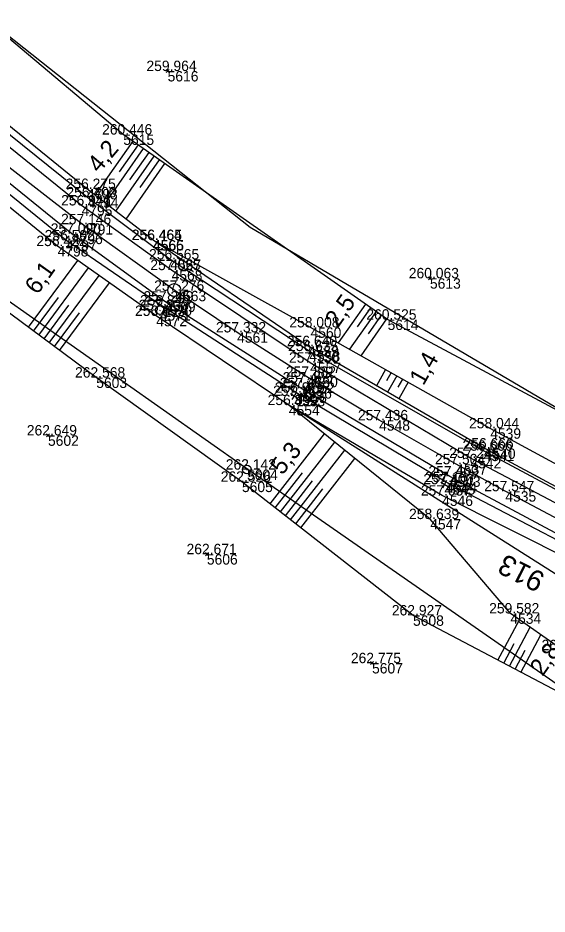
# Model space of a CAD drawing. Extents: x -809970 to -809480, y -1011362 to -1010672.
# Drawn here: x -809711.9 to -809650.7, y -1011259.5 to -1011155.9 of the extents above; entities that cross this region are included whole.
import ezdxf

# ---------------------------------------------------------------- set-up
doc = ezdxf.new("R2010")
doc.units = 0
for name, color, linetype in [('Vrstva 1', 7, 'Continuous'), ('Vrstva 4', 7, 'Continuous'), ('Vrstva 48', 7, 'Continuous'), ('Vrstva 49', 7, 'Continuous'), ('Vrstva 53', 7, 'Continuous'), ('Vrstva 60', 7, 'Continuous'), ('Vrstva 61', 7, 'Continuous'), ('Vrstva 63', 7, 'Continuous'), ('Vrstva 7', 7, 'Continuous')]:
    doc.layers.add(name, color=color, linetype=linetype)

msp = doc.modelspace()

# ---------------------------------------------------------------- linework, layer by layer
at = {"layer": 'Vrstva 1'}
msp.add_lwpolyline([(-809626.11, -1011225.69), (-809635.65, -1011220.96), (-809646.77, -1011215.28), (-809655.53, -1011210.64), (-809661.22, -1011207.52), (-809670.13, -1011202.44), (-809678.48, -1011197.41), (-809686.56, -1011192.28), (-809693.71, -1011187.47), (-809704.48, -1011179.77), (-809716.3, -1011170.61)], dxfattribs=at)
at = {"layer": 'Vrstva 4'}
for points in [[(-809514.07, -1011276.67), (-809539.83, -1011264.26), (-809562.29, -1011253.6), (-809585.06, -1011242.59), (-809604.03, -1011233.74), (-809622.75, -1011224.34), (-809635.98, -1011217.78), (-809658.04, -1011205.96), (-809678.21, -1011194.44), (-809694.3, -1011183.84), (-809703.86, -1011176.66), (-809724.9, -1011159.78), (-809744.11, -1011141.6), (-809762.15, -1011122.16), (-809774.57, -1011106.33), (-809789.63, -1011085.97), (-809801.28, -1011067.08), (-809811.54, -1011048.02), (-809817.16, -1011036.69), (-809823.08, -1011022.98)], [(-809514.73, -1011277.55), (-809539.87, -1011265.31), (-809562.72, -1011254.42), (-809585.31, -1011243.69), (-809604.51, -1011234.26), (-809623.3, -1011225.16), (-809636.52, -1011218.94), (-809659.57, -1011206.8), (-809678.11, -1011195.78), (-809694.14, -1011185.08), (-809704.56, -1011177.6), (-809725.72, -1011160.53), (-809745.22, -1011142.43), (-809763.07, -1011123.23), (-809775.62, -1011107.42), (-809790.76, -1011086.7), (-809802.43, -1011068.09), (-809812.88, -1011048.59), (-809818.37, -1011037.45), (-809824.5, -1011023.86)], [(-809516.72, -1011279.86), (-809541.72, -1011267.84), (-809564.36, -1011257.13), (-809585.64, -1011247.05), (-809605.96, -1011237.21), (-809624.35, -1011228.4), (-809638.66, -1011221.38), (-809661.97, -1011208.93), (-809679.17, -1011198.73), (-809694.94, -1011188.71), (-809705.67, -1011180.87), (-809727.9, -1011162.91), (-809747.29, -1011144.85), (-809765.46, -1011125.12), (-809778.44, -1011109.55), (-809793.36, -1011088.57), (-809805.27, -1011069.6), (-809816.07, -1011050.21), (-809821.49, -1011039.16), (-809826.21, -1011028.82)], [(-809517.34, -1011281.17), (-809542.25, -1011268.91), (-809565.05, -1011257.74), (-809585.85, -1011248.03), (-809606.19, -1011237.96), (-809624.44, -1011229.46), (-809639.03, -1011221.78), (-809662.37, -1011209.59), (-809679.75, -1011199.24), (-809695.35, -1011189.16), (-809706.37, -1011181.63), (-809728.71, -1011163.52), (-809748.04, -1011145.82), (-809766.46, -1011126.18), (-809779.35, -1011110.29), (-809779.4, -1011110.26), (-809794.33, -1011089.31), (-809806.51, -1011070.34), (-809817.46, -1011050.77), (-809822.78, -1011039.81), (-809827.65, -1011029.26)]]:
    msp.add_lwpolyline(points, dxfattribs=at)
at = {"layer": 'Vrstva 48'}
for p, q in [((-809698.64, -1011170.17), (-809703.01, -1011176.41)), ((-809698.02, -1011170.59), (-809700.22, -1011173.73)), ((-809697.41, -1011171.03), (-809701.82, -1011177.33)), ((-809696.18, -1011171.89), (-809700.63, -1011178.25)), ((-809696.79, -1011171.46), (-809699.01, -1011174.62)), ((-809694.95, -1011172.74), (-809699.44, -1011179.17)), ((-809695.56, -1011172.32), (-809697.8, -1011175.51)), ((-809710.71, -1011191.69), (-809704.98, -1011183.96)), ((-809709.5, -1011192.58), (-809703.76, -1011184.83)), ((-809708.3, -1011193.47), (-809702.53, -1011185.69)), ((-809707.09, -1011194.36), (-809701.31, -1011186.56)), ((-809710.1, -1011192.13), (-809707.24, -1011188.26)), ((-809708.9, -1011193.03), (-809706.02, -1011189.14)), ((-809671.72, -1011189), (-809674.87, -1011193.5)), ((-809671.11, -1011189.44), (-809672.66, -1011191.65)), ((-809707.69, -1011193.92), (-809704.81, -1011190.02)), ((-809670.49, -1011189.86), (-809673.55, -1011194.23)), ((-809669.88, -1011190.3), (-809671.39, -1011192.45)), ((-809669.26, -1011190.72), (-809672.24, -1011194.97)), ((-809669.4, -1011196.57), (-809670.45, -1011198.44)), ((-809668.74, -1011196.93), (-809669.27, -1011197.88)), ((-809668.09, -1011197.3), (-809669.15, -1011199.19)), ((-809667.44, -1011197.67), (-809667.97, -1011198.62)), ((-809666.78, -1011198.04), (-809667.85, -1011199.94)), ((-809682.74, -1011212.09), (-809676.44, -1011204.02)), ((-809681.56, -1011213.01), (-809675.27, -1011204.96)), ((-809680.37, -1011213.93), (-809674.1, -1011205.9)), ((-809679.19, -1011214.86), (-809672.93, -1011206.84)), ((-809682.15, -1011212.55), (-809679, -1011208.52)), ((-809680.96, -1011213.47), (-809677.82, -1011209.45)), ((-809679.78, -1011214.4), (-809676.65, -1011210.38)), ((-809656.38, -1011230.18), (-809653.91, -1011225.5)), ((-809655.05, -1011230.88), (-809652.67, -1011226.37)), ((-809653.72, -1011231.58), (-809651.44, -1011227.23)), ((-809655.72, -1011230.53), (-809654.51, -1011228.23)), ((-809654.39, -1011231.23), (-809653.22, -1011229.01))]:
    msp.add_line(p, q, dxfattribs=at)
at = {"layer": 'Vrstva 49'}
for p, q in [((-809694.78, -1011161.89), (-809694.42, -1011162.24)), ((-809694.78, -1011162.24), (-809694.42, -1011161.89)), ((-809664.43, -1011185.85), (-809664.07, -1011186.2)), ((-809664.43, -1011186.2), (-809664.07, -1011185.85)), ((-809708.61, -1011204.01), (-809708.26, -1011204.36)), ((-809708.61, -1011204.36), (-809708.26, -1011204.01)), ((-809690.23, -1011217.74), (-809689.88, -1011218.1)), ((-809690.23, -1011218.1), (-809689.88, -1011217.74)), ((-809671.12, -1011230.34), (-809670.77, -1011230.69)), ((-809671.12, -1011230.69), (-809670.77, -1011230.34))]:
    msp.add_line(p, q, dxfattribs=at)
for points in [[(-809511.61, -1011271.23), (-809536.39, -1011258.33), (-809560.01, -1011246.27), (-809576.21, -1011238.32), (-809612.21, -1011219.9), (-809615.12, -1011217.12), (-809615.79, -1011215.73), (-809619.54, -1011223.55), (-809624.01, -1011221.32), (-809620.33, -1011213.39), (-809626.47, -1011211.63), (-809636.4, -1011208.19), (-809641.71, -1011205.47), (-809669.15, -1011190.8), (-809699.73, -1011169.4), (-809726.54, -1011146.85), (-809748.5, -1011124.91), (-809769.57, -1011100.55), (-809784.98, -1011078.51), (-809794.37, -1011063.91), (-809798.01, -1011059.09), (-809806.77, -1011045.25), (-809814.25, -1011034.46), (-809820.96, -1011021.87)], [(-809517.95, -1011282.18), (-809542.49, -1011269.58), (-809565.63, -1011258.32), (-809585.98, -1011248.4), (-809606.44, -1011238.24), (-809621.62, -1011231.05), (-809624.45, -1011230.4), (-809627.73, -1011228.86), (-809639.59, -1011222.81), (-809662.84, -1011211.14), (-809680.58, -1011200.68), (-809695.92, -1011190.37), (-809707.33, -1011182.3), (-809729.57, -1011164.32), (-809748.84, -1011146.41), (-809766.98, -1011126.93), (-809779.99, -1011110.78), (-809794.75, -1011089.67), (-809807.08, -1011070.6), (-809818.27, -1011051.22), (-809824.25, -1011040.29), (-809829.11, -1011030.23)], [(-809513.01, -1011276.14), (-809534.58, -1011266.09), (-809539.77, -1011263.86), (-809561.92, -1011253.16), (-809584.64, -1011241.91), (-809603.49, -1011232.88), (-809619.73, -1011225.04), (-809620.87, -1011223.99), (-809623.85, -1011222.57), (-809625.32, -1011222.49), (-809635.81, -1011217.56), (-809657.91, -1011205.7), (-809678.34, -1011193.87), (-809696.27, -1011181.61), (-809696.31, -1011181.59), (-809703.94, -1011175.69), (-809724.27, -1011159.21)], [(-809624.01, -1011221.32), (-809625.48, -1011221.25), (-809635.66, -1011215.12), (-809657.28, -1011203.37), (-809678.07, -1011191.7), (-809696.27, -1011181.61), (-809696.31, -1011181.59)], [(-809528.41, -1011284.67), (-809557.05, -1011271.63), (-809578.05, -1011261.94), (-809594.42, -1011254.32), (-809626.26, -1011240.21), (-809627.58, -1011240.01), (-809623.67, -1011231.94), (-809628.13, -1011229.78), (-809632.16, -1011237.96), (-809631.7, -1011238.19), (-809633.92, -1011240.11), (-809638.94, -1011239.66), (-809644.87, -1011236.23), (-809666.21, -1011225), (-809686, -1011209.54), (-809702.86, -1011197.5), (-809722.79, -1011182.74)], [(-809628.13, -1011229.78), (-809630.07, -1011228.4), (-809632.43, -1011226.95), (-809647.88, -1011221.39), (-809680.58, -1011200.68)], [(-809632.16, -1011237.96), (-809640.18, -1011233.65), (-809648.89, -1011229.02), (-809654.95, -1011224.77), (-809664.22, -1011213.86), (-809680.58, -1011200.68)]]:
    msp.add_lwpolyline(points, dxfattribs=at)
at = {"layer": 'Vrstva 53'}
msp.add_line((-809685.46, -1011208.11), (-809685.38, -1011208.16), dxfattribs=at)
for points in [[(-809817.83, -1011024.91), (-809805.06, -1011048.21), (-809777.13, -1011090.84), (-809773.31, -1011095.41), (-809752.3, -1011120.38), (-809722.41, -1011150.52), (-809685.06, -1011180.11), (-809638.61, -1011207.44), (-809624.45, -1011211.08), (-809620, -1011212.86), (-809615.56, -1011215.28), (-809614.76, -1011215.85), (-809598.39, -1011227.55), (-809488.36, -1011283.38)], [(-809479.96, -1011306.98), (-809541.53, -1011278.39), (-809624.88, -1011241.51), (-809627.72, -1011240.25), (-809632.39, -1011238.49), (-809632.72, -1011238.43), (-809644.97, -1011236.14), (-809685.42, -1011208.04), (-809719.22, -1011184.3), (-809751.99, -1011157.11), (-809779.01, -1011125.97), (-809796.54, -1011101.19), (-809810.89, -1011076.81), (-809836.26, -1011028.53)]]:
    msp.add_lwpolyline(points, dxfattribs=at)
msp.add_circle((-809685.42, -1011208.14), 0.499, dxfattribs=at)
at = {"layer": 'Vrstva 60'}
for p, q in [((-809694.6, -1011162.06), (-809694.6, -1011162.06)), ((-809699.73, -1011169.4), (-809699.73, -1011169.4)), ((-809703.94, -1011175.69), (-809703.94, -1011175.69)), ((-809703.86, -1011176.66), (-809703.86, -1011176.66)), ((-809704.56, -1011177.6), (-809704.56, -1011177.6)), ((-809704.48, -1011179.77), (-809704.48, -1011179.77)), ((-809705.67, -1011180.87), (-809705.67, -1011180.87)), ((-809707.33, -1011182.3), (-809707.33, -1011182.3)), ((-809706.37, -1011181.63), (-809706.37, -1011181.63)), ((-809696.31, -1011181.59), (-809696.31, -1011181.59)), ((-809696.27, -1011181.61), (-809696.27, -1011181.61)), ((-809694.3, -1011183.84), (-809694.3, -1011183.84)), ((-809694.14, -1011185.08), (-809694.14, -1011185.08)), ((-809664.25, -1011186.02), (-809664.25, -1011186.02)), ((-809693.71, -1011187.47), (-809693.71, -1011187.47)), ((-809695.35, -1011189.16), (-809695.35, -1011189.16)), ((-809694.94, -1011188.71), (-809694.94, -1011188.71)), ((-809695.92, -1011190.37), (-809695.92, -1011190.37)), ((-809695.5, -1011189.71), (-809695.5, -1011189.71)), ((-809669.15, -1011190.8), (-809669.15, -1011190.8)), ((-809686.56, -1011192.28), (-809686.56, -1011192.28)), ((-809678.07, -1011191.7), (-809678.07, -1011191.7)), ((-809678.34, -1011193.87), (-809678.34, -1011193.87)), ((-809678.21, -1011194.44), (-809678.21, -1011194.44)), ((-809678.11, -1011195.78), (-809678.11, -1011195.78)), ((-809702.86, -1011197.5), (-809702.86, -1011197.5)), ((-809678.48, -1011197.41), (-809678.48, -1011197.41)), ((-809679.17, -1011198.73), (-809679.17, -1011198.73)), ((-809678.83, -1011198.07), (-809678.83, -1011198.07)), ((-809679.95, -1011199.62), (-809679.95, -1011199.62)), ((-809679.75, -1011199.24), (-809679.75, -1011199.24)), ((-809680.58, -1011200.68), (-809680.58, -1011200.68)), ((-809670.13, -1011202.44), (-809670.13, -1011202.44)), ((-809657.28, -1011203.37), (-809657.28, -1011203.37)), ((-809708.44, -1011204.19), (-809708.44, -1011204.19)), ((-809658.04, -1011205.96), (-809658.04, -1011205.96)), ((-809657.91, -1011205.7), (-809657.91, -1011205.7)), ((-809659.57, -1011206.8), (-809659.57, -1011206.8)), ((-809685.42, -1011208.14), (-809685.42, -1011208.14)), ((-809661.22, -1011207.52), (-809661.22, -1011207.52)), ((-809661.97, -1011208.93), (-809661.97, -1011208.93)), ((-809686, -1011209.54), (-809686, -1011209.54)), ((-809662.57, -1011209.83), (-809662.57, -1011209.83)), ((-809662.37, -1011209.59), (-809662.37, -1011209.59)), ((-809662.84, -1011211.14), (-809662.84, -1011211.14)), ((-809655.53, -1011210.64), (-809655.53, -1011210.64)), ((-809664.22, -1011213.86), (-809664.22, -1011213.86)), ((-809690.06, -1011217.92), (-809690.06, -1011217.92)), ((-809654.95, -1011224.77), (-809654.95, -1011224.77)), ((-809666.21, -1011225), (-809666.21, -1011225)), ((-809670.95, -1011230.52), (-809670.95, -1011230.52))]:
    msp.add_line(p, q, dxfattribs=at)
at = {"layer": 'Vrstva 7'}
for p, q in [((-809695.54, -1011189.69), (-809695.46, -1011189.74)), ((-809680.37, -1011199.35), (-809679.53, -1011199.89)), ((-809679.68, -1011199.19), (-809680.22, -1011200.04)), ((-809663, -1011209.58), (-809662.13, -1011210.08)), ((-809662.32, -1011209.4), (-809662.81, -1011210.27))]:
    msp.add_line(p, q, dxfattribs=at)
for centre, radius in [((-809693.84, -1011187.38), 0.75), ((-809695.5, -1011189.71), 0.5)]:
    msp.add_circle(centre, radius, dxfattribs=at)

# ---------------------------------------------------------------- texts
at = {"layer": 'Vrstva 48'}
for s, rotation, p in [('4,2', 49.937, (-809702.54, -1011173.94)), ('6,1', 54.7503, (-809709.65, -1011188)), ('2,5', 55.0089, (-809674.91, -1011191.84)), ('1,4', 60.6951, (-809665.01, -1011198.52)), ('5,3', 51.1502, (-809681.34, -1011208.86)), ('2,8', 54.9661, (-809651.22, -1011232.13))]:
    msp.add_text(s, height=2, rotation=rotation, dxfattribs=at).set_placement(p)
at = {"layer": 'Vrstva 60'}
for s, p in [('5616', (-809694.6, -1011163.26)), ('5615', (-809699.73, -1011170.6)), ('4793', (-809703.94, -1011176.89)), ('4794', (-809703.86, -1011177.86)), ('4795', (-809704.56, -1011178.8)), ('4791', (-809704.48, -1011180.97)), ('4796', (-809705.67, -1011182.07)), ('4798', (-809707.33, -1011183.5)), ('4797', (-809706.37, -1011182.83)), ('4566', (-809696.31, -1011182.79)), ('4565', (-809696.27, -1011182.81)), ('4567', (-809694.3, -1011185.04)), ('4568', (-809694.14, -1011186.28)), ('5613', (-809664.25, -1011187.22)), ('4563', (-809693.71, -1011188.67)), ('4570', (-809695.35, -1011190.36)), ('4569', (-809694.94, -1011189.92)), ('4572', (-809695.92, -1011191.57)), ('4571', (-809695.5, -1011190.91)), ('5614', (-809669.15, -1011192)), ('4561', (-809686.56, -1011193.47)), ('4560', (-809678.07, -1011192.9)), ('4559', (-809678.34, -1011195.07)), ('4558', (-809678.21, -1011195.64)), ('4557', (-809678.11, -1011196.98)), ('5603', (-809702.86, -1011198.7)), ('4550', (-809678.48, -1011198.61)), ('4556', (-809679.17, -1011199.93)), ('4552', (-809678.83, -1011199.27)), ('4553', (-809679.95, -1011200.82)), ('4555', (-809679.75, -1011200.44)), ('4554', (-809680.58, -1011201.88)), ('4548', (-809670.13, -1011203.64)), ('4539', (-809657.28, -1011204.57)), ('5602', (-809708.44, -1011205.39)), ('4541', (-809658.04, -1011207.16)), ('4540', (-809657.91, -1011206.9)), ('4542', (-809659.57, -1011208)), ('5604', (-809685.42, -1011209.34)), ('4537', (-809661.22, -1011208.72)), ('4543', (-809661.97, -1011210.13)), ('5605', (-809686, -1011210.74)), ('4545', (-809662.57, -1011211.03)), ('4544', (-809662.37, -1011210.79)), ('4546', (-809662.84, -1011212.34)), ('4535', (-809655.53, -1011211.84)), ('4547', (-809664.22, -1011215.06)), ('5606', (-809690.06, -1011219.12)), ('4534', (-809654.95, -1011225.97)), ('5608', (-809666.21, -1011226.2)), ('5607', (-809670.95, -1011231.71))]:
    msp.add_text(s, height=1.2, dxfattribs=at).set_placement(p)
at = {"layer": 'Vrstva 61'}
for s, p in [('259.964', (-809697.05, -1011162.06)), ('260.446', (-809702.18, -1011169.4)), ('256.275', (-809706.4, -1011175.69)), ('256.400', (-809706.31, -1011176.66)), ('256.941', (-809706.92, -1011177.6)), ('257.146', (-809706.93, -1011179.77)), ('257.090', (-809708.12, -1011180.87)), ('256.422', (-809709.78, -1011182.3)), ('256.502', (-809708.82, -1011181.63)), ('256.464', (-809698.76, -1011181.59)), ('256.465', (-809698.73, -1011181.61)), ('256.565', (-809696.75, -1011183.84)), ('257.025', (-809696.6, -1011185.08)), ('260.063', (-809666.7, -1011186.02)), ('257.276', (-809696.16, -1011187.47)), ('257.249', (-809697.4, -1011188.71)), ('257.233', (-809697.95, -1011189.71)), ('256.840', (-809697.8, -1011189.16)), ('256.853', (-809698.37, -1011190.37)), ('258.008', (-809680.52, -1011191.7)), ('260.525', (-809671.61, -1011190.8)), ('257.332', (-809689.01, -1011192.28)), ('256.640', (-809680.8, -1011193.87)), ('256.635', (-809680.66, -1011194.44)), ('257.130', (-809680.56, -1011195.78)), ('262.568', (-809705.31, -1011197.5)), ('257.382', (-809680.92, -1011197.41)), ('257.378', (-809681.63, -1011198.73)), ('257.485', (-809681.29, -1011198.07)), ('257.163', (-809682.4, -1011199.62)), ('256.979', (-809682.2, -1011199.24)), ('256.899', (-809683.03, -1011200.68)), ('257.436', (-809672.58, -1011202.44)), ('262.649', (-809710.89, -1011204.19)), ('258.044', (-809659.73, -1011203.37)), ('256.666', (-809660.49, -1011205.96)), ('256.666', (-809660.36, -1011205.7)), ('257.245', (-809662.03, -1011206.8)), ('262.142', (-809687.87, -1011208.14)), ('257.504', (-809663.67, -1011207.52)), ('257.469', (-809664.43, -1011208.93)), ('262.526', (-809688.45, -1011209.54)), ('257.400', (-809665.02, -1011209.83)), ('257.167', (-809664.82, -1011209.59)), ('257.057', (-809665.3, -1011211.14)), ('257.547', (-809657.98, -1011210.64)), ('258.639', (-809666.67, -1011213.86)), ('262.671', (-809692.41, -1011217.92)), ('259.582', (-809657.4, -1011224.77)), ('262.927', (-809668.66, -1011225)), ('260.020', (-809651.34, -1011229.02)), ('262.775', (-809673.4, -1011230.52))]:
    msp.add_text(s, height=1.2, dxfattribs=at).set_placement(p)
at = {"layer": 'Vrstva 63'}
msp.add_text('913', height=2.4, rotation=152.9342, dxfattribs=at).set_placement((-809650.76, -1011220.27))

doc.saveas('drawing.dxf')
